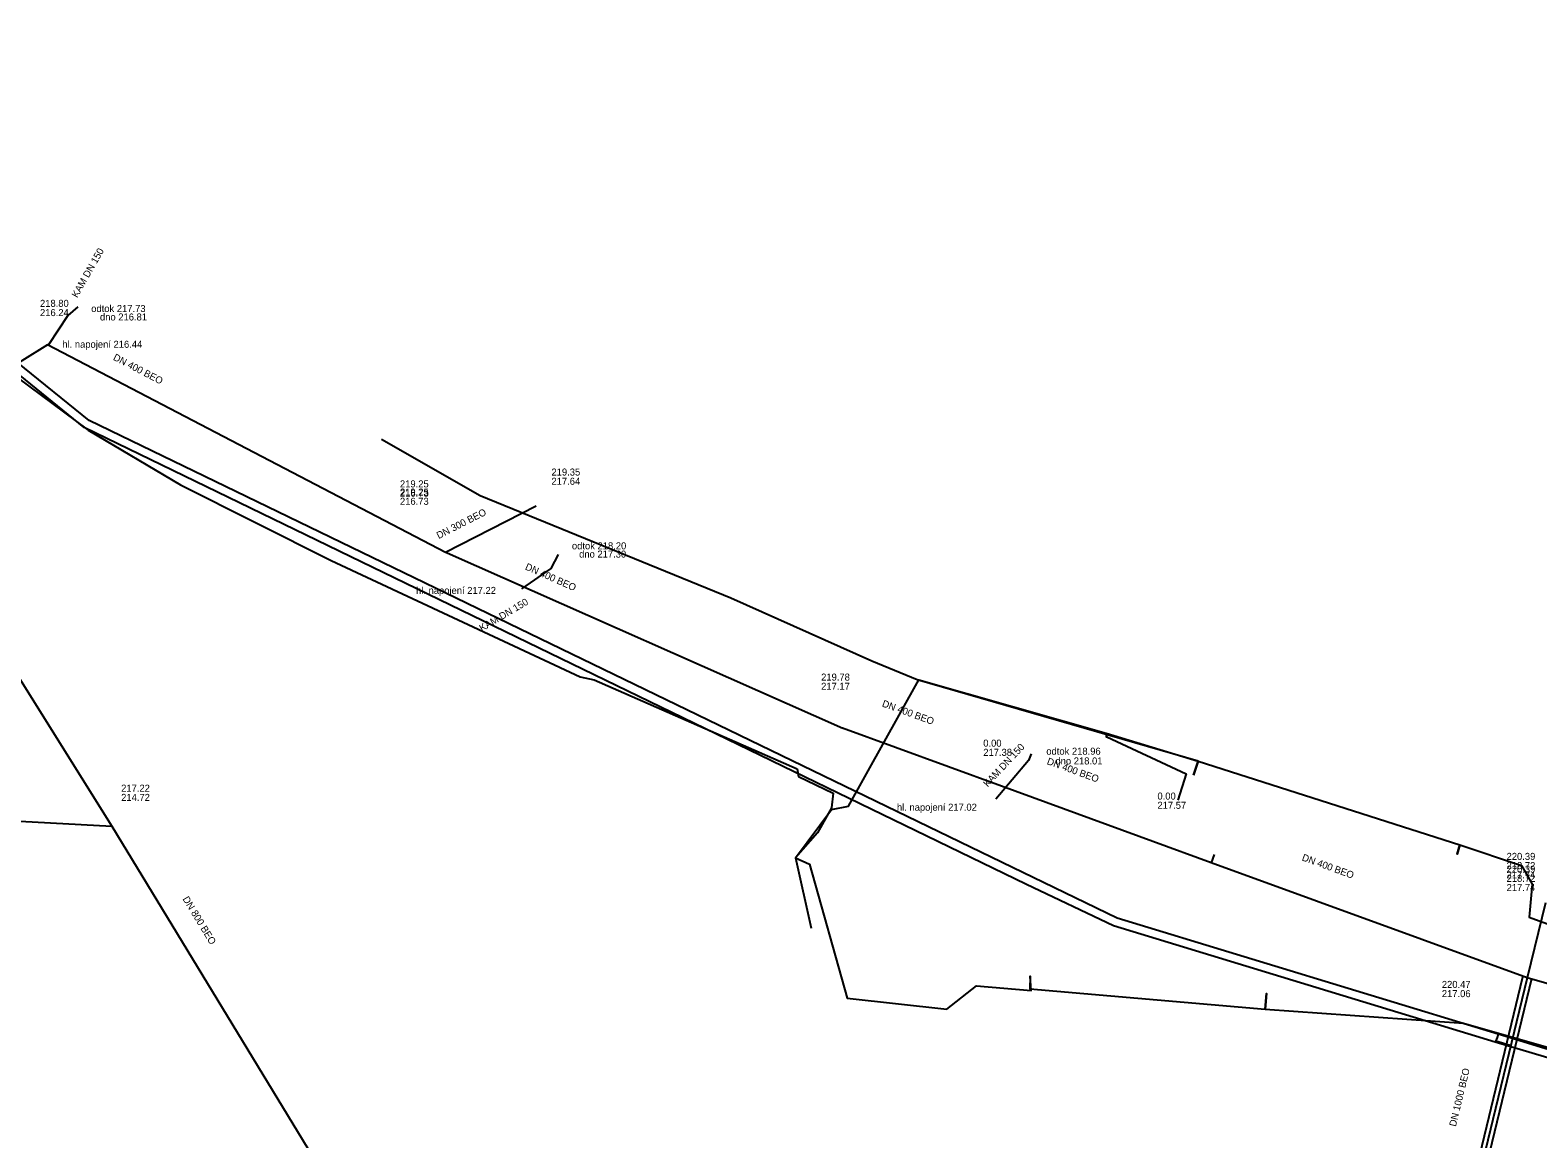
# Model space of a CAD drawing. Extents: x -598233 to -596890, y -1157848 to -1156431.
# Drawn here: x -598002.9 to -597831.2, y -1157579.3 to -1157453 of the extents above; entities that cross this region are included whole.
import ezdxf

# ---------------------------------------------------------------- set-up
doc = ezdxf.new("R2010")
doc.units = 0
for name, color, linetype in [('BODY', 7, 'Continuous'), ('BODY_VYSKY_CELE', 7, 'Continuous'), ('Vrstva 10', 7, 'Continuous'), ('Vrstva 12', 7, 'Continuous'), ('Vrstva 13', 7, 'Continuous'), ('Vrstva 55', 7, 'Continuous'), ('Vrstva 9', 7, 'Continuous')]:
    doc.layers.add(name, color=color, linetype=linetype)

msp = doc.modelspace()

# ---------------------------------------------------------------- linework, layer by layer
at = {"layer": 'BODY'}
for points in [[(-597997.47, -1157484.51), (-597998.61, -1157485.51), (-598000.8, -1157488.86)], [(-597942.78, -1157512.73), (-597943.6, -1157514.33), (-597946.94, -1157516.65)], [(-597888.91, -1157535.44), (-597889.22, -1157536.19), (-597892.94, -1157540.59)]]:
    msp.add_lwpolyline(points, dxfattribs=at)
at = {"layer": 'Vrstva 10'}
for p, q in [((-597839.38, -1157587.41), (-597832.95, -1157560.83)), ((-597831.98, -1157561.06), (-597838.41, -1157587.65))]:
    msp.add_line(p, q, dxfattribs=at)
at = {"layer": 'Vrstva 13'}
for points in [[(-597603.06, -1157619.91), (-597739.73, -1157592.24), (-597778.6, -1157583.03), (-597825.15, -1157570.63), (-597835.74, -1157567.34), (-597879.15, -1157554.13), (-597996.18, -1157497.47), (-598020.69, -1157477.67), (-598071.79, -1157432.81), (-598174.31, -1157397.68), (-598184.13, -1157393.93), (-598189.83, -1157391.7), (-598214.48, -1157379.52), (-598223.33, -1157356.15)], [(-597606.76, -1157620.59), (-597740, -1157593.21), (-597778.8, -1157584.05), (-597825.25, -1157571.5), (-597836.11, -1157568.28), (-597879.54, -1157555.02), (-597889.47, -1157550.32), (-597996.74, -1157498.27), (-598021.24, -1157478.37), (-598022.8, -1157476.49), (-598023.12, -1157476.1)], [(-597835.74, -1157567.34), (-597835.87, -1157567.73), (-597836.01, -1157568.12), (-597834.39, -1157568.61)]]:
    msp.add_lwpolyline(points, dxfattribs=at)
at = {"layer": 'Vrstva 55'}
for points in [[(-598052.96, -1157451.09), (-598048.35, -1157455.75), (-598035.07, -1157466.75), (-598023.59, -1157476.63), (-598017.2, -1157481.95), (-598007.11, -1157490.58), (-597996.27, -1157498.58), (-597985.78, -1157504.8), (-597968.63, -1157513.43), (-597940.29, -1157526.66), (-597938.69, -1157527.01), (-597915.58, -1157537.14), (-597915.4, -1157538.03), (-597911.45, -1157539.92), (-597911.67, -1157541.59), (-597913.27, -1157544.43), (-597915.76, -1157547.27)], [(-597870.44, -1157537.85), (-597869.9, -1157536.25), (-597901.9, -1157527.01), (-597907.05, -1157524.87), (-597923.11, -1157517.71), (-597951.66, -1157506.04), (-597962.9, -1157499.65)], [(-597915.76, -1157547.27), (-597911.67, -1157541.76), (-597909.72, -1157541.4), (-597901.72, -1157527.01), (-597880.38, -1157533.08), (-597880.35, -1157533.55), (-597880.38, -1157533.08), (-597869.9, -1157536.25), (-597870.44, -1157537.85)], [(-597880.32, -1157533.5), (-597871.27, -1157537.72), (-597872.24, -1157540.72)], [(-597870.44, -1157537.85), (-597869.9, -1157536.25), (-597840.11, -1157545.78), (-597840.42, -1157546.86), (-597840.11, -1157545.78), (-597833.11, -1157548.16), (-597831.87, -1157550.29), (-597832.22, -1157554.02), (-597815.16, -1157560.24), (-597805.92, -1157562.2), (-597805.56, -1157562.91), (-597780.54, -1157569.69), (-597766.46, -1157573.04), (-597750.51, -1157576.93), (-597746.38, -1157577.66), (-597719.58, -1157583.51), (-597711.54, -1157585.12), (-597658.12, -1157596.01)], [(-597915.76, -1157547.27), (-597914.16, -1157547.98), (-597909.89, -1157563.26), (-597898.52, -1157564.51), (-597895.14, -1157561.84), (-597888.94, -1157562.39), (-597889.05, -1157560.75), (-597889.08, -1157562.21), (-597862.27, -1157564.49), (-597862.15, -1157562.71), (-597862.27, -1157564.49), (-597839.69, -1157566.11), (-597811.96, -1157574.03)], [(-597915.76, -1157547.27), (-597913.97, -1157555.3)]]:
    msp.add_lwpolyline(points, dxfattribs=at)
at = {"layer": 'Vrstva 9'}
for p, q in [((-598000.9, -1157488.86), (-598017.07, -1157498.89)), ((-597955.6, -1157512.5), (-598000.9, -1157488.86)), ((-598016.99, -1157506.29), (-597993.58, -1157543.65)), ((-597945.3, -1157507.24), (-597955.6, -1157512.5)), ((-597892.32, -1157539.12), (-597910.4, -1157532.52)), ((-597875.07, -1157545.43), (-597892.32, -1157539.12)), ((-598004.07, -1157543.1), (-597993.58, -1157543.65)), ((-597993.58, -1157543.65), (-597963.97, -1157592.35)), ((-597868.08, -1157546.91), (-597868.42, -1157547.85)), ((-597830.38, -1157552.4), (-597832.47, -1157560.95)), ((-597832.47, -1157560.95), (-597838.9, -1157587.53))]:
    msp.add_line(p, q, dxfattribs=at)
for points in [[(-597910.36, -1157532.54), (-597955.4, -1157512.58), (-597955.6, -1157512.5)], [(-597832.47, -1157560.95), (-597868.42, -1157547.85), (-597875.07, -1157545.43)], [(-597783.98, -1157574.94), (-597817.03, -1157565.37), (-597832.47, -1157560.95)]]:
    msp.add_lwpolyline(points, dxfattribs=at)

# ---------------------------------------------------------------- texts
at = {"layer": 'BODY_VYSKY_CELE'}
for rotation, p in [(60.5043, (-597997.53, -1157483.56)), (30.7105, (-597951.46, -1157521.54)), (46.8679, (-597893.88, -1157539.27))]:
    msp.add_text('KAM DN 150', height=0.8, rotation=rotation, dxfattribs=at).set_placement(p)
for s, p in [('odtok 217.73', (-597995.94, -1157485.12)), ('dno 216.81', (-597994.94, -1157486.08)), ('hl. napojení 216.44', (-597999.23, -1157489.19)), ('odtok 218.20', (-597941.21, -1157512.14)), ('dno 217.30', (-597940.39, -1157513.08)), ('hl. napojení 217.22', (-597958.96, -1157517.22)), ('odtok 218.96', (-597887.2, -1157535.53)), ('dno 218.01', (-597886.16, -1157536.64)), ('hl. napojení 217.02', (-597904.21, -1157541.91))]:
    msp.add_text(s, height=0.8, dxfattribs=at).set_placement(p)
at = {"layer": 'Vrstva 12'}
for s, p in [('218.80', (-598001.77, -1157484.53)), ('216.24', (-598001.77, -1157485.58)), ('219.25', (-597960.79, -1157505.09)), ('219.35', (-597943.54, -1157503.74)), ('217.64', (-597943.54, -1157504.79)), ('219.25', (-597960.79, -1157506.02)), ('216.73', (-597960.79, -1157506.14)), ('216.73', (-597960.79, -1157507.07)), ('219.78', (-597912.84, -1157527.09)), ('217.17', (-597912.84, -1157528.14)), ('0.00', (-597894.38, -1157534.61)), ('217.38', (-597894.38, -1157535.66)), ('217.22', (-597992.53, -1157539.74)), ('214.72', (-597992.53, -1157540.79)), ('0.00', (-597874.55, -1157540.64)), ('217.57', (-597874.55, -1157541.69)), ('220.39', (-597834.8, -1157547.51)), ('218.72', (-597834.8, -1157548.56)), ('220.39', (-597834.8, -1157548.96)), ('217.74', (-597834.8, -1157549.61)), ('218.72', (-597834.8, -1157550.01)), ('217.74', (-597834.8, -1157551.06)), ('220.47', (-597842.17, -1157562.09)), ('217.06', (-597842.17, -1157563.14))]:
    msp.add_text(s, height=0.8, dxfattribs=at).set_placement(p)
for s, rotation, p in [('DN 400 BEO', 332.4387, (-597993.52, -1157490.53)), ('DN 300 BEO', 27.0657, (-597956.38, -1157510.98)), ('DN 400 BEO', 336.0827, (-597946.61, -1157514.41)), ('DN 400 BEO', 339.9385, (-597905.97, -1157530.02)), ('DN 400 BEO', 339.9385, (-597887.2, -1157536.59)), ('DN 400 BEO', 339.9904, (-597858.17, -1157547.55)), ('DN 800 BEO', 301.3024, (-597985.57, -1157551.96)), ('DN 1000 BEO', 76.4014, (-597840.58, -1157577.93))]:
    msp.add_text(s, height=0.8, rotation=rotation, dxfattribs=at).set_placement(p)

doc.saveas('drawing.dxf')
